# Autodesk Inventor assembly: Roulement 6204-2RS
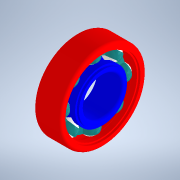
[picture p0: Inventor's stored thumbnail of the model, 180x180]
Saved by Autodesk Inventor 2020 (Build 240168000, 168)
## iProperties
Created: 2003-06
Part Number: Roulement 6204-2RS
Document SubType Name: Assembly
Designer: Bruno
Author: Bruno
Sending System: SolidWorks 2011
Last Author: Professeur
Last Saved: 2014-11-10
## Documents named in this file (5)
- D:\Téléchargements-2016-17\scoot_elec\pièces à assembler\ROULEMENT 6204-2RS\Roulement 6204-2RS.iam
- D:\Téléchargements-2016-17\scoot_elec\pièces à assembler\ROULEMENT 6204-2RS\Bague intérieure 6204-2RS.ipt
- D:\Téléchargements-2016-17\scoot_elec\pièces à assembler\ROULEMENT 6204-2RS\Cage 6204-2RS.ipt
- D:\Téléchargements-2016-17\scoot_elec\pièces à assembler\ROULEMENT 6204-2RS\Billes 6204-2RS.ipt
- D:\Téléchargements-2016-17\scoot_elec\pièces à assembler\ROULEMENT 6204-2RS\Bague extérieure 6204-2RS.ipt
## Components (11 placed, 4 different names)
1. Bague intérieure 6204-2RS:1
2. Cage 6204-2RS:1
3. Billes 6204-2RS:1
4. Billes 6204-2RS:2
5. Billes 6204-2RS:3
6. Billes 6204-2RS:4
7. Billes 6204-2RS:5
8. Billes 6204-2RS:6
9. Billes 6204-2RS:7
10. Billes 6204-2RS:8
11. Bague extérieure 6204-2RS:1
